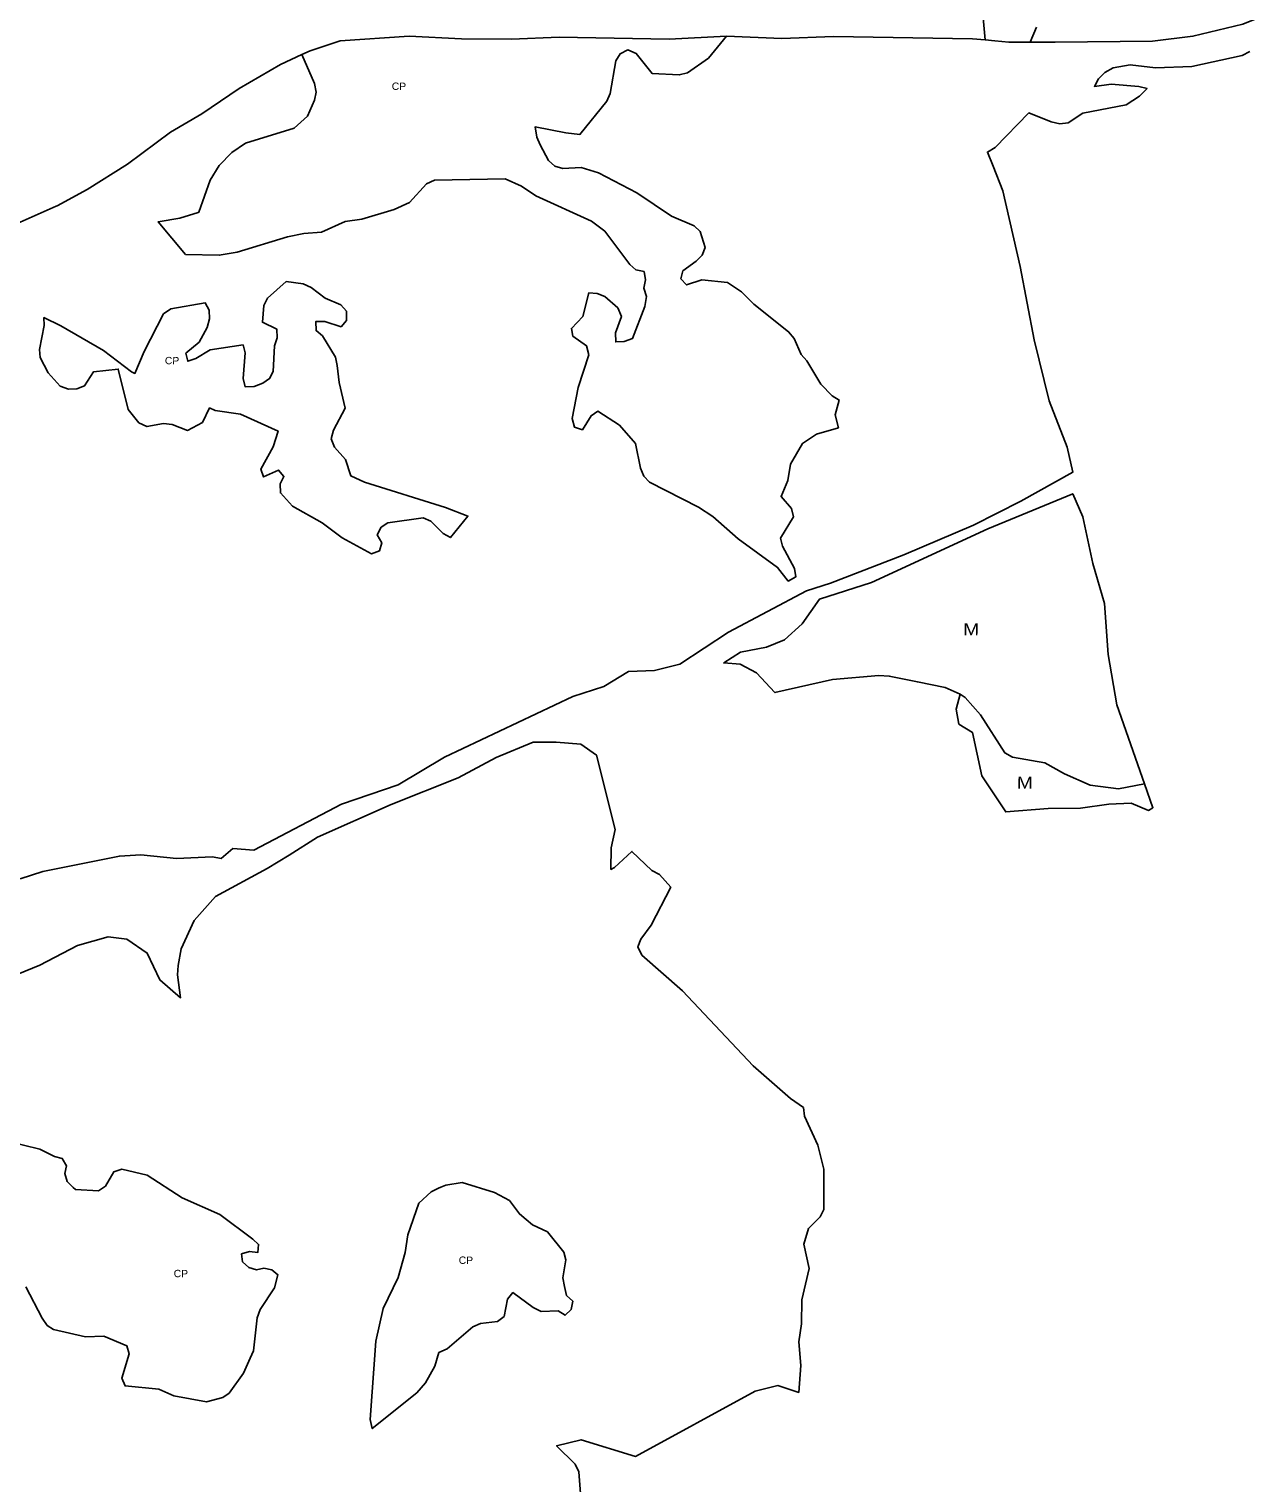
# Model space of a CAD drawing. Extents: x 713589 to 726391, y 7177764 to 7191819.
# Drawn here: x 719806 to 720865, y 7181207 to 7182472 of the extents above; entities that cross this region are included whole.
import ezdxf
from ezdxf.enums import TextEntityAlignment as Align

# ---------------------------------------------------------------- set-up
doc = ezdxf.new("R2010")
doc.units = 0
doc.header["$LTSCALE"] = 2.6
doc.layers.add('63', color=7, linetype='Continuous', lineweight=25)

msp = doc.modelspace()

# ---------------------------------------------------------------- linework, layer by layer
at = {"layer": '63'}
for points in [[(720676.98, 7182460.7), (720698.59, 7182460.69), (720783.16, 7182461.67), (720818.37, 7182465.94), (720861.81, 7182476.46), (720953.96, 7182513.96)], [(720635.85, 7182485.01), (720637.7, 7182462.65)], [(720043.3, 7182449.85), (720050.65, 7182453.24), (720076.64, 7182461.79), (720136.87, 7182466.06), (720182.28, 7182463.75), (720225.71, 7182463.41), (720267.18, 7182465.05), (720362.94, 7182463.38), (720412.63, 7182465.94)], [(720412.63, 7182465.94), (720397.07, 7182446.68), (720378.97, 7182434.18), (720371.73, 7182432.2), (720348.04, 7182433.52), (720334.22, 7182450.97), (720326.98, 7182453.93), (720320.4, 7182450.64), (720316.45, 7182444.39), (720311.51, 7182416.09), (720308.54, 7182409.51), (720285.24, 7182380.49), (720273.01, 7182381.91), (720246.2, 7182386.92), (720247.66, 7182377.93), (720250.62, 7182371.35), (720257.86, 7182357.85), (720263.45, 7182352.92), (720270.36, 7182350.94), (720286.49, 7182351.6), (720301.29, 7182346.99), (720334.86, 7182329.54), (720364.8, 7182309.46), (720384.54, 7182300.9), (720389.8, 7182295.97), (720394.08, 7182282.14), (720391.45, 7182275.56), (720386.51, 7182270.3), (720374.66, 7182261.74), (720373.01, 7182254.83), (720377.95, 7182249.57), (720391.44, 7182253.84), (720413.49, 7182251.54), (720425.66, 7182243.64), (720436.52, 7182232.78), (720466.79, 7182208.75), (720471.73, 7182202.82), (720477.65, 7182189), (720482.58, 7182183.41), (720494.75, 7182163.33), (720504.63, 7182153.13), (720510.77, 7182149.32), (720507.25, 7182136.54), (720510.03, 7182125.27), (720491.13, 7182119.57), (720478.95, 7182111.67), (720468.42, 7182093.57), (720466.11, 7182079.42), (720460.19, 7182065.6), (720469.4, 7182055.07), (720471.04, 7182047.83), (720459.85, 7182029.08), (720461.49, 7182022.17), (720472.02, 7182002.75), (720473.01, 7181995.51), (720466.42, 7181991.89), (720457.21, 7182003.74), (720422.99, 7182028.75), (720400.95, 7182048.17), (720388.45, 7182056.07), (720345.67, 7182077.8), (720340.74, 7182083.06), (720338.1, 7182089.98), (720333.5, 7182111.7), (720319.68, 7182127.49), (720300.93, 7182139.67), (720295, 7182135.72), (720287.43, 7182123.55), (720280.52, 7182125.85), (720278.55, 7182133.42), (720283.61, 7182160.42), (720293.04, 7182188.71), (720291.07, 7182196.6), (720279.22, 7182204.83), (720277.91, 7182211.74), (720287.78, 7182221.94), (720293.05, 7182242.67), (720300.29, 7182242.01), (720306.87, 7182239.38), (720318.38, 7182229.51), (720321.34, 7182221.94), (720316.08, 7182207.79), (720316.4, 7182199.89), (720323.64, 7182200.22), (720330.88, 7182202.85), (720341.75, 7182230.82), (720343.07, 7182239.37), (720340.76, 7182246.61), (720342.41, 7182253.85), (720341.1, 7182261.09), (720333.86, 7182262.74), (720328.59, 7182267.35), (720306.88, 7182296.31), (720295.36, 7182304.87)], [(720412.63, 7182465.94), (720461, 7182464.03), (720505.75, 7182465.66), (720626.85, 7182463.67), (720637.7, 7182462.65)], [(720637.7, 7182462.65), (720646.03, 7182461.87), (720658.44, 7182460.7), (720676.98, 7182460.7)], [(720676.98, 7182460.7), (720682.25, 7182473.81)], [(719526.23, 7182367.51), (719536.29, 7182367.77), (719562.62, 7182373.03), (719593.22, 7182362.82), (719622.84, 7182350.64), (719683.71, 7182318.38), (719709.05, 7182307.52), (719763.67, 7182292.37), (719788.02, 7182299.61), (719829.74, 7182318.04), (719830.47, 7182318.36), (719856.8, 7182332.5), (719891.69, 7182354.54), (719929.21, 7182382.51), (719956.52, 7182398.3), (719988.78, 7182420.34), (720024.98, 7182441.4), (720043.3, 7182449.85)], [(720295.36, 7182304.87), (720246.99, 7182326.92), (720234.49, 7182335.48), (720220.34, 7182341.74), (720158.8, 7182340.76), (720151.89, 7182337.47), (720137.08, 7182321.35), (720123.59, 7182315.1), (720095.62, 7182306.88), (720081.14, 7182304.58), (720060.4, 7182295.36), (720045.27, 7182294.38), (720030.79, 7182291.42), (719987.02, 7182277.94), (719971.55, 7182275.31), (719942.26, 7182275.97), (719918.35, 7182304.39), (719937.25, 7182307.62), (719953.32, 7182312.66), (719953.89, 7182312.92), (719963.67, 7182340.79), (719971.57, 7182353.3), (719982.43, 7182364.81), (719994.27, 7182372.71), (720036.73, 7182385.86), (720048.25, 7182396.39), (720054.5, 7182410.21), (720055.82, 7182417.12), (720054.5, 7182424.69), (720043.3, 7182449.85)], [(720867.86, 7182452.52), (720861.28, 7182449.23), (720817.51, 7182439.69), (720785.92, 7182438.38), (720763.87, 7182441.02), (720749.07, 7182438.39), (720741.82, 7182434.44), (720736.23, 7182428.85), (720732.69, 7182422.27), (720747.22, 7182424.09), (720771.27, 7182422.13), (720778.53, 7182420.33), (720772.1, 7182413.71), (720760.25, 7182406.14), (720722.73, 7182398.91), (720709.9, 7182390.68), (720702.66, 7182389.7), (720695.09, 7182391.34), (720675.69, 7182399.1), (720646.56, 7182369.01), (720639.75, 7182365.17), (720644.62, 7182352.86), (720653.07, 7182331.46), (720668.19, 7182265.64), (720680.36, 7182201.8), (720693.51, 7182148.82), (720708.97, 7182108.34), (720713.9, 7182086.62), (720668.82, 7182061.29), (720627.68, 7182040.56), (720567.12, 7182014.58), (720503.28, 7181990.03), (720482.22, 7181983.33), (720414.42, 7181947.47), (720372.04, 7181919.56), (720350.25, 7181914.12), (720327.54, 7181913.14)], [(720616.01, 7181893.61), (720602.93, 7181899.2), (720578.78, 7181904.2), (720554.24, 7181909.3), (720545.23, 7181909.6), (720504.97, 7181906.13), (720454.86, 7181894.88), (720438.77, 7181912.13), (720424.62, 7181919.7), (720410.37, 7181920.62), (720424.95, 7181929.9), (720447.66, 7181934.5), (720463.12, 7181940.75), (720478.59, 7181954.57), (720493.57, 7181976.09), (720538.82, 7181990.56), (720640.18, 7182037.27), (720713.9, 7182067.86), (720722.78, 7182047.79), (720731.33, 7182007.31), (720741.52, 7181972.43), (720744.81, 7181928), (720752.37, 7181884.23), (720776.44, 7181815.38)], [(720327.54, 7181913.14), (720306.15, 7181900.11), (720279.17, 7181891.56), (720167.6, 7181838.6), (720127.12, 7181814.58), (720077.76, 7181797.81), (720001.74, 7181757.67), (719983.31, 7181759.32), (719973.27, 7181750.46), (719965.65, 7181752.09), (719934.3, 7181750.58), (719903.35, 7181753.86), (719884.79, 7181752.64), (719818.18, 7181739.18), (719798.53, 7181732.87)], [(720616.01, 7181893.61), (720612.51, 7181880.31), (720614.81, 7181867.48), (720626.66, 7181860.23), (720634.88, 7181822.39), (720655.63, 7181791.1), (720692.46, 7181793.95), (720720.76, 7181794.27), (720745.44, 7181797.89), (720764.86, 7181798.54), (720779.79, 7181792.34), (720783.68, 7181794.68), (720776.44, 7181815.38)], [(720616.01, 7181893.61), (720620.36, 7181890.68), (720633.73, 7181875.49), (720654.98, 7181842.38), (720661.44, 7181838.66), (720689.65, 7181833.66), (720706.84, 7181824.1), (720729.03, 7181814.35), (720753.66, 7181811.07), (720776.44, 7181815.38)], [(719778.54, 7181642.67), (719815.4, 7181657.8), (719848.31, 7181674.91), (719874.96, 7181682.47), (719891.29, 7181680.36), (719908.99, 7181668.31), (719919.91, 7181644.88), (719937.88, 7181629.44), (719935.2, 7181649.47), (719935.79, 7181657.46), (719938.43, 7181671.95), (719949.8, 7181696.68), (719968.42, 7181717.6), (720013.13, 7181741.96), (720032.34, 7181753.39), (720057.02, 7181769.18), (720121.2, 7181797.47), (720179.44, 7181820.82), (720212.35, 7181838.26), (720244.61, 7181851.75), (720264.68, 7181851.74), (720286.07, 7181850.09), (720299.56, 7181840.55), (720316, 7181775.72), (720312.38, 7181759.92), (720312.22, 7181740.98), (720315.25, 7181742.62), (720330.49, 7181756.73), (720347.81, 7181740.17), (720354.39, 7181736.55), (720364.26, 7181725.69), (720347.14, 7181692.46), (720338.25, 7181680.28), (720335.62, 7181673.7), (720339.24, 7181666.46)], [(720339.24, 7181666.46), (720374.44, 7181635.52), (720435.97, 7181570.03), (720468.54, 7181541.72), (720479.73, 7181533.82), (720480.71, 7181526.25), (720492.23, 7181501.24), (720497.49, 7181480.18), (720497.48, 7181445.3), (720494.19, 7181438.72), (720483.99, 7181428.52), (720480.03, 7181415.03), (720484.64, 7181393.97), (720478.38, 7181366.65), (720478.05, 7181345.59), (720475.74, 7181330.13), (720477.38, 7181309.4), (720475.54, 7181286.11), (720457.42, 7181292.16), (720437.67, 7181287.22), (720333.47, 7181230.41), (720286.29, 7181244.8), (720264.97, 7181239.64), (720281.24, 7181223.54), (720284.2, 7181216.96), (720288.8, 7181160.36)], [(719803.46, 7181377.96), (719817.6, 7181350.65), (719821.88, 7181344.39), (719827.47, 7181340.77), (719855.11, 7181334.51), (719871.24, 7181334.84), (719891.31, 7181326.61), (719893.28, 7181319.7), (719886.7, 7181298.31), (719889.66, 7181291.73), (719918.95, 7181288.76), (719932.11, 7181283.17), (719960.41, 7181277.9), (719974.56, 7181281.51), (719980.15, 7181285.46), (719992.66, 7181302.9), (719998.59, 7181315.73), (720001.22, 7181322.31), (720004.52, 7181350.94), (720007.15, 7181358.18), (720019.66, 7181376.94), (720022.62, 7181388.45), (720017.36, 7181392.73), (720010.45, 7181394.05), (720003.87, 7181392.73), (719997.28, 7181394.71), (719991.69, 7181399.65), (719991.03, 7181406.56), (719997.94, 7181408.53), (720005.18, 7181407.87), (720005.84, 7181414.78), (720000.91, 7181419.39), (719971.95, 7181440.78), (719939.38, 7181455.27), (719908.78, 7181475.02), (719886.73, 7181480.29), (719879.82, 7181477.98), (719872.58, 7181465.48), (719866.65, 7181461.53), (719846.44, 7181462.45), (719844.55, 7181464.31), (719839.34, 7181469.44), (719837.37, 7181476.35), (719838.69, 7181483.26), (719835.07, 7181489.51), (719828.16, 7181491.16), (719815.66, 7181497.74), (719787.03, 7181504.66)]]:
    msp.add_lwpolyline(points, dxfattribs=at)
for points in [[(720068.93, 7182115.69), (720070.9, 7182123.26), (720081.11, 7182142.34), (720075.85, 7182164.72), (720074.21, 7182179.53), (720072.56, 7182186.77), (720061.38, 7182205.2), (720055.78, 7182209.81), (720055.45, 7182217.7), (720063.35, 7182217.7), (720077.5, 7182213.09), (720082.11, 7182218.69), (720082.11, 7182226.59), (720077.18, 7182232.18), (720063.69, 7182238.11), (720051.51, 7182247.32), (720044.6, 7182250.61), (720029.79, 7182252.59), (720013.67, 7182238.11), (720010.37, 7182231.53), (720009.06, 7182217.06), (720021.56, 7182211.13), (720021.89, 7182203.56), (720019.58, 7182196.65), (720018.59, 7182174.27), (720015.3, 7182168.02), (720009.38, 7182164.07), (720001.81, 7182161.11), (719994.24, 7182160.79), (719992.26, 7182168.03), (719994.24, 7182190.4), (719992.27, 7182197.31), (719963.64, 7182193.04), (719951.13, 7182185.47), (719944.22, 7182183.17), (719942.58, 7182190.08), (719954.1, 7182199.62), (719961.01, 7182212.46), (719962.99, 7182220.02), (719962.66, 7182227.59), (719959.37, 7182233.85), (719929.42, 7182228.59), (719923.17, 7182224.31), (719906.38, 7182191.73), (719898.28, 7182172.56), (719895.19, 7182173.84), (719870.84, 7182192.6), (719833.66, 7182213.99), (719819.04, 7182221.14), (719819.18, 7182214.13), (719815.23, 7182193.4), (719815.89, 7182186.49), (719822.79, 7182172.99), (719833.32, 7182161.47), (719840.56, 7182158.84), (719847.8, 7182159.17), (719854.38, 7182161.8), (719862.28, 7182173.97), (719883.67, 7182176.27), (719892.22, 7182141.06), (719901.76, 7182129.54), (719908.67, 7182126.25), (719923.15, 7182128.88), (719930.72, 7182128.22), (719943.88, 7182122.95), (719957.05, 7182129.86), (719963.16, 7182142.57), (719967.91, 7182140.26), (719989.96, 7182136.96), (720022.68, 7182122.36), (720018.58, 7182108.79), (720007.72, 7182089.38), (720010.02, 7182082.46), (720023.18, 7182088.39), (720027.79, 7182082.79), (720024.5, 7182076.54), (720024.83, 7182068.64), (720035.35, 7182057.12), (720061.02, 7182042.64), (720078.46, 7182029.47), (720104.12, 7182015.65), (720111.03, 7182018.28), (720113.01, 7182025.19), (720109.06, 7182032.1), (720112.35, 7182038.68), (720118.28, 7182042.63), (720148.88, 7182046.9), (720155.46, 7182043.94), (720166.32, 7182033.41), (720172.57, 7182029.79), (720187.81, 7182048.38), (720168.3, 7182055.98), (720097.88, 7182078.04), (720085.94, 7182083.42), (720081.43, 7182097.59), (720071.89, 7182108.45)], [(720270.41, 7181385.78), (720271.73, 7181378.21), (720273.7, 7181370.31), (720278.96, 7181365.37), (720277.65, 7181358.13), (720272.38, 7181353.2), (720266.46, 7181357.15), (720251.65, 7181356.49), (720244.74, 7181359.78), (720226.97, 7181372.95), (720222.36, 7181367.03), (720219.4, 7181352.22), (720213.48, 7181347.61), (720198.67, 7181345.97), (720192.08, 7181343.01), (720169.7, 7181323.93), (720162.68, 7181320.72), (720159.12, 7181308.94), (720150.99, 7181294.4), (720143.35, 7181285.78), (720104.68, 7181254.51), (720102.89, 7181262.4), (720107.84, 7181330.52), (720114.1, 7181359.15), (720127.27, 7181386.13), (720133.19, 7181407.85), (720135.5, 7181422.99), (720145.05, 7181450.63), (720155.91, 7181460.5), (720162.16, 7181463.79), (720164.32, 7181464.65), (720168.74, 7181466.42), (720182.89, 7181468.72), (720210.86, 7181459.83), (720224.02, 7181452.92), (720232.58, 7181441.4), (720238.5, 7181436.46), (720244.09, 7181431.85), (720256.93, 7181425.6), (720271.4, 7181408.15), (720273.05, 7181401.24)]]:
    msp.add_lwpolyline(points, close=True, dxfattribs=at)

# ---------------------------------------------------------------- texts
for s, height, width, p in [('CP', 6.4, 1.05, (720127.81, 7182419.16)), ('CP', 6.4, 1.05, (719930.46, 7182180.47)), ('M', 10.4, 1.2, (720625.46, 7181944.71)), ('M', 10.4, 1.2, (720672.17, 7181811.34)), ('CP', 6.4, 1.05, (720186.06, 7181397.83)), ('CP', 6.4, 1.05, (719938.14, 7181386.24))]:
    msp.add_text(s, height=height, rotation=359.062, dxfattribs=dict(at, width=width)).set_placement(p, align=Align.CENTER)

doc.saveas('drawing.dxf')
